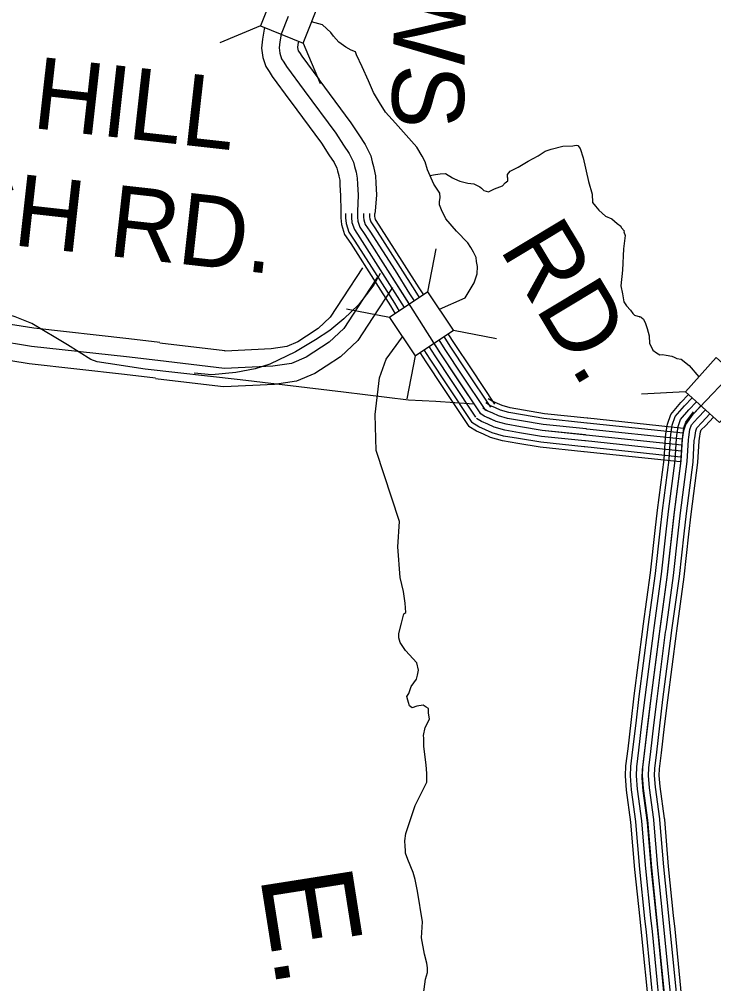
# Model space of a CAD drawing. Extents: x 1551132 to 1791609, y 378168 to 563823.
# Drawn here: x 1647521 to 1651105, y 423447 to 428427 of the extents above; entities that cross this region are included whole.
import ezdxf

# ---------------------------------------------------------------- set-up
doc = ezdxf.new("R2010")
doc.units = 0
for name, color, linetype in [('DESIGN - DRAINAGE - Bridges and Cross Drains Size Text', 7, 'Continuous'), ('DESIGN - ROW - Right-of-Way and Easement Labels', 7, 'Continuous'), ('DESIGN - TRANSPORTATION - Text', 7, 'Continuous'), ('SURVEY - DRAINAGE - Storm Sewer', 7, 'Continuous'), ('SURVEY - PROPERTY - Owners', 7, 'Continuous'), ('SURVEY - TRANSPORTATION - Roads', 7, 'Continuous')]:
    doc.layers.add(name, color=color, linetype=linetype)

msp = doc.modelspace()

# ---------------------------------------------------------------- linework, layer by layer
at = {"layer": 'DESIGN - TRANSPORTATION - Text'}
for points in [[(1649689.434, 426930.053), (1649822.414, 426988.779), (1649868.13, 427066.006), (1649884.904, 427111.841), (1649886.863, 427150.908), (1649881.504, 427176.017), (1649879.763, 427196.076), (1649866.13, 427224.294), (1649852.447, 427248.503), (1649836.764, 427272.737), (1649777.582, 427333.572), (1649722.417, 427396.356), (1649701.017, 427442.699), (1649689.359, 427468.883), (1649689.559, 427484.909), (1649693.834, 427506.893), (1649692.117, 427528.952), (1649660.726, 427575.419), (1649627.694, 427649.946), (1649616.211, 427690.156), (1649600.611, 427720.398), (1649573.212, 427766.816), (1649462.865, 427890.386), (1649411.624, 427947.121), (1649380.292, 427997.589), (1649348.951, 428048.065), (1649323.735, 428108.475), (1649290.677, 428181.002), (1649261.495, 428243.47), (1649255.703, 428259.571), (1649233.82, 428267.854), (1649206.029, 428282.221), (1649170.388, 428308.705), (1649142.797, 428339.098), (1649129.064, 428359.298), (1649086.182, 428398.174), (1649029.933, 428413.641)], [(1649639.444, 427619.512), (1649669.476, 427625.312), (1649693.476, 427629.146), (1649721.467, 427630.954), (1649757.266, 427608.679), (1649767.207, 427602.595), (1649795.098, 427590.387), (1649836.981, 427580.086), (1649866.93, 427577.87), (1649898.779, 427561.628), (1649906.729, 427555.561), (1649918.629, 427543.46), (1649942.545, 427535.285), (1649974.627, 427551.086), (1650014.701, 427566.828), (1650028.801, 427582.753), (1650042.868, 427592.67), (1650042.984, 427608.696), (1650041.001, 427610.712), (1650041.101, 427624.729), (1650055.217, 427642.655), (1650095.325, 427662.405), (1650147.498, 427694.09), (1650199.647, 427721.765), (1650235.788, 427745.549), (1650265.829, 427755.358), (1650325.886, 427770.967), (1650377.843, 427772.608), (1650395.851, 427776.483), (1650403.834, 427774.425), (1650415.717, 427760.325), (1650431.35, 427712.148), (1650458.424, 427589.787), (1650477.924, 427523.552), (1650479.616, 427481.484), (1650495.448, 427461.342), (1650513.29, 427441.191), (1650547.031, 427410.907), (1650578.897, 427396.674), (1650606.696, 427372.44), (1650626.57, 427358.281), (1650628.52, 427352.264), (1650644.362, 427332.122), (1650642.345, 427330.13), (1650648.195, 427310.063), (1650639.703, 427242.028), (1650634.903, 427131.9), (1650626.312, 427049.84), (1650634.012, 427009.73), (1650641.695, 426967.621), (1650655.536, 426947.495), (1650675.352, 426925.32), (1650687.21, 426907.211), (1650697.143, 426899.136), (1650725.059, 426890.927), (1650723.06, 426890.944), (1650731.034, 426888.885), (1650735.001, 426884.852), (1650742.951, 426878.785), (1650752.775, 426856.685), (1650762.575, 426830.584), (1650772.292, 426792.458), (1650773.992, 426752.39), (1650785.825, 426730.273), (1650791.724, 426718.214), (1650809.607, 426704.072), (1650827.515, 426693.939), (1650841.515, 426695.839), (1650859.465, 426691.714), (1650889.406, 426687.497), (1650901.347, 426681.405), (1650915.288, 426675.297), (1650937.238, 426671.138), (1650978.962, 426638.804), (1651029.002, 426581.352)], [(1649358.675, 426386.963), (1649380.241, 426574.793), (1649414.248, 426672.329), (1649499.355, 426786.932)], [(1649607.35, 423393.451), (1649617.867, 423471.503), (1649628.083, 423505.488), (1649628.242, 423529.53), (1649624.4, 423553.589), (1649612.7, 423599.748), (1649597.259, 423684.001), (1649601.792, 423766.094), (1649576.835, 423924.532), (1649565.227, 423984.717), (1649553.46, 424020.851), (1649525.911, 424089.161), (1649514.12, 424121.295), (1649514.211, 424135.321), (1649512.361, 424157.371), (1649510.545, 424185.43), (1649516.795, 424223.448), (1649563.735, 424367.344), (1649602.226, 424443.196), (1649624.517, 424487.113), (1649624.817, 424533.181), (1649621.109, 424577.282), (1649609.726, 424671.518), (1649610.009, 424715.586), (1649608.101, 424729.62), (1649616.368, 424769.629), (1649630.534, 424795.572), (1649638.667, 424815.547), (1649632.851, 424843.631), (1649633.009, 424867.673), (1649621.059, 424875.765), (1649605.126, 424885.899), (1649573.094, 424880.115), (1649549.036, 424872.273), (1649535.103, 424882.39), (1649529.211, 424898.457), (1649527.295, 424910.491), (1649521.42, 424930.558), (1649531.528, 424946.517), (1649543.761, 424982.485), (1649572.01, 425020.352), (1649576.144, 425040.353), (1649582.31, 425066.354), (1649572.561, 425104.48), (1649514.97, 425166.99), (1649487.246, 425209.257), (1649479.404, 425233.35), (1649479.554, 425255.383), (1649493.904, 425309.377), (1649506.221, 425357.361), (1649516.254, 425363.303), (1649512.57, 425411.404), (1649504.962, 425471.556), (1649487.438, 425543.799), (1649474.48, 425702.154), (1649483.346, 425834.299), (1649363.474, 426199.6), (1649358.675, 426386.963)]]:
    msp.add_lwpolyline(points, dxfattribs=at)
at = {"layer": 'SURVEY - DRAINAGE - Storm Sewer'}
for p, q in [((1648765.471, 428393.363), (1648556.414, 428304.608)), ((1648985.723, 428304.36), (1649074.487, 428095.312)), ((1649629.107, 427019.468), (1649672.443, 427242.428)), ((1649432.135, 426886.596), (1649209.183, 426929.933)), ((1649762.004, 426822.48), (1649984.93, 426779.168)), ((1649564.965, 426689.641), (1649521.645, 426466.715)), ((1650958.95, 426503.296), (1650732.141, 426491.416))]:
    msp.add_line(p, q, dxfattribs=at)
for points in [[(1648765.471, 428393.363), (1648985.773, 428304.343), (1649074.793, 428524.654), (1648854.474, 428613.658)], [(1649432.135, 426886.596), (1649564.99, 426689.616), (1649762.004, 426822.48), (1649629.107, 427019.468)], [(1650958.95, 426503.296), (1651135.546, 426344.317), (1651294.5, 426520.88), (1651117.937, 426679.867)]]:
    msp.add_lwpolyline(points, close=True, dxfattribs=at)
at = {"layer": 'SURVEY - PROPERTY - Owners'}
for points in [[(1648909.47, 428441.208), (1648872.587, 428349.439), (1648865.404, 428311.088), (1648861.904, 428279.454), (1648866.112, 428251.27), (1648875.354, 428223.253), (1648887.17, 428205.111), (1648900.945, 428182.952), (1648991.701, 428059.923), (1649155.455, 427838.068), (1649194.846, 427777.616), (1649224.395, 427733.273), (1649245.953, 427689.006), (1649251.736, 427666.922), (1649259.436, 427636.813), (1649265.136, 427606.72), (1649266.827, 427574.661), (1649270.269, 427518.551), (1649267.452, 427434.466), (1649267.161, 427404.431), (1649268.961, 427384.389), (1649278.66, 427354.255), (1649304.276, 427315.962), (1649434.223, 427112.457), (1649692.125, 426705.455), (1649901.22, 426390.347)], [(1648788.706, 428383.974), (1648785.081, 428374.948), (1648775.623, 428324.447), (1648770.448, 428277.712), (1648777.548, 428230.211), (1648792.905, 428183.635), (1648810.638, 428156.401), (1648825.813, 428132), (1648917.677, 428007.464), (1648918.719, 428006.055), (1649080.907, 427786.325), (1649119.106, 427727.698), (1649145.522, 427688.055), (1649160.48, 427657.346), (1649163.921, 427644.188), (1649170.055, 427620.229), (1649170.846, 427617.129), (1649174.88, 427595.836), (1649176.271, 427569.494), (1649179.471, 427517.293), (1649180.371, 427438.441), (1649180.371, 427426.324)], [(1648962.002, 428314.663), (1648958.735, 428297.205), (1648956.968, 428281.263), (1648958.177, 428273.162), (1648961.052, 428264.437), (1648966.718, 428255.737), (1648979.043, 428235.92), (1649066.541, 428117.308), (1649067.566, 428115.925), (1649232.953, 427891.853), (1649273.577, 427829.501), (1649306.385, 427780.275), (1649334.801, 427721.915), (1649343.017, 427690.556), (1649349.292, 427666.038), (1649351.525, 427657.271), (1649358.959, 427618.029), (1649360.967, 427580.036), (1649364.658, 427519.86), (1649358.492, 427436.332), (1649355.85, 427423.682)], [(1650999.136, 426388.181), (1651234.739, 426636.637), (1651378.127, 426785.458), (1651566.123, 426997.939), (1651612.572, 427045.565), (1651679.096, 427103), (1651817.784, 427179.777), (1651998.722, 427284.188), (1652121.385, 427357.107), (1652177.526, 427374.599), (1652225.616, 427386.149), (1652261.657, 427391.816), (1652327.564, 427385.174), (1652539.234, 427361.124), (1653150.228, 427287.189), (1653709.273, 427215.754), (1654418.581, 427121.668)], [(1648246.609, 426757.839), (1648085.946, 426776.881), (1647596.491, 426831.449), (1647408.537, 426861.041), (1647360.622, 426868.125), (1647346.797, 426873.466), (1647232.508, 426944.427), (1647042.504, 427058.621), (1646944.848, 427097.505), (1646907.682, 427109.506), (1646858.475, 427116.273), (1646810.885, 427111.181), (1646765.427, 427100.922), (1646727.445, 427080.255), (1646690.454, 427049.096), (1646676.529, 427019.92), (1646610.073, 426849.599)], [(1649292.86, 427143.866), (1649191.67, 426988.895), (1649126.055, 426888.509), (1649063.965, 426830.708), (1649003.316, 426791.174), (1648958.959, 426762.256), (1648901.377, 426737.455), (1648820.454, 426726.013), (1648583.46, 426713.963), (1648581.576, 426714.188), (1648246.284, 426754.272)], [(1649383.549, 427114.824), (1649351.925, 427055.781), (1649271.819, 426952.453), (1649195.929, 426880.759), (1649124.247, 426819.608), (1649050.465, 426771.106), (1648947.168, 426709.955), (1648814.354, 426646.695), (1648738.464, 426621.394), (1648639.383, 426602.41), (1648515.003, 426591.868), (1648424.355, 426600.302)], [(1649368.808, 427094.273), (1649267.61, 426939.286), (1649195.937, 426829.633), (1649120.047, 426758.989), (1649001.983, 426682.021), (1648926.101, 426649.336), (1648829.12, 426635.628), (1648580.36, 426622.977), (1648235.518, 426664.203)], [(1648235.518, 426664.203), (1648075.171, 426683.204), (1647583.933, 426737.971), (1647394.312, 426767.822), (1647336.422, 426776.381), (1647304.556, 426788.706), (1647183.351, 426863.958), (1647000.505, 426973.852), (1646912.891, 427008.736), (1646886.616, 427017.22), (1646857.042, 427021.287), (1646826.326, 427018.003), (1646798.977, 427011.828), (1646780.885, 427001.986), (1646766.777, 426990.103), (1646763.111, 426982.419), (1646759.519, 426973.219)], [(1649447.756, 427042.722), (1649346.55, 426887.71), (1649268.577, 426768.431), (1649178.346, 426684.437), (1649104.339, 426636.186), (1649046.707, 426598.619), (1648951.801, 426557.734), (1648838.128, 426541.667), (1648577.135, 426528.4), (1648559.618, 426530.491), (1648224.326, 426570.576)], [(1648224.843, 426574.126), (1648064.813, 426593.084), (1647571.85, 426648.044), (1647380.629, 426678.145), (1647313.139, 426688.128), (1647263.924, 426707.162), (1647136.069, 426786.547), (1646960.098, 426892.3), (1646882.15, 426923.343), (1646866.35, 426928.443), (1646855.667, 426929.909), (1646841.184, 426928.368), (1646803.226, 426801.156)], [(1649868.013, 426440.398), (1649671.667, 426453.323), (1649529.804, 426460.69), (1649194.362, 426501.949), (1648661.224, 426565.117), (1648169.986, 426619.885), (1647980.365, 426649.736), (1647922.475, 426658.294), (1647890.609, 426670.62), (1647769.404, 426745.872), (1647586.558, 426855.766), (1647498.943, 426890.65), (1647472.669, 426899.134), (1647443.095, 426903.201), (1647412.379, 426899.917), (1647385.029, 426893.742), (1647366.938, 426883.9), (1647360.105, 426878.142)], [(1650941.046, 426228.268), (1650446.491, 426280.278), (1650220.713, 426304.028), (1650108.865, 426322.912), (1650034.975, 426335.487), (1649983.018, 426350.346), (1649921.303, 426378.413), (1649897.412, 426392.614)], [(1650857.346, 423315.4), (1650818.147, 423708.194), (1650784.457, 424032.86), (1650764.215, 424279.325), (1650741.383, 424443.705), (1650735.841, 424509.598), (1650738.158, 424551.866), (1650748.766, 424637.893), (1650780.69, 424909.992), (1650825.123, 425254.084), (1650865.189, 425546.15), (1650901.48, 425870.275), (1650935.346, 426134.349), (1650942.146, 426246.444), (1650950.554, 426304.453), (1650960.762, 426334.413), (1650999.136, 426388.181)]]:
    msp.add_lwpolyline(points, dxfattribs=at)
at = {"layer": 'SURVEY - TRANSPORTATION - Roads'}
for points in [[(1649180.638, 427425.04), (1649180.404, 427400.965), (1649183.454, 427367.014), (1649199.837, 427316.129), (1649231.686, 427268.511), (1649361.058, 427065.914), (1649436.406, 426947.003)], [(1649205.354, 427424.799), (1649205.137, 427401.956), (1649207.829, 427371.964), (1649222.303, 427326.996), (1649252.378, 427282.037), (1649381.916, 427079.181), (1649457.289, 426960.228)], [(1649236.353, 427424.499), (1649236.145, 427403.19), (1649238.395, 427378.181), (1649250.486, 427340.621), (1649278.327, 427298.995), (1649408.065, 427095.815), (1649483.472, 426976.829)], [(1649267.352, 427424.199), (1649267.161, 427404.431), (1649268.961, 427384.389), (1649278.66, 427354.255), (1649304.276, 427315.962), (1649434.223, 427112.457), (1649692.125, 426705.455), (1649901.22, 426390.347)], [(1649267.352, 427424.199), (1649267.161, 427404.431), (1649268.961, 427384.389), (1649278.66, 427354.255), (1649304.276, 427315.962), (1649434.223, 427112.457), (1649509.655, 426993.421)], [(1649298.352, 427423.899), (1649298.177, 427405.673), (1649299.526, 427390.598), (1649306.835, 427367.889), (1649330.226, 427332.93), (1649460.381, 427129.099), (1649535.837, 427010.013)], [(1649329.351, 427423.599), (1649329.184, 427406.907), (1649330.092, 427396.815), (1649335.017, 427381.514), (1649356.175, 427349.888), (1649486.53, 427145.733), (1649562.02, 427026.613)], [(1649355.067, 427423.349), (1649354.917, 427407.94), (1649355.45, 427401.965), (1649358.392, 427392.823), (1649377.7, 427363.964), (1649508.23, 427159.542), (1649583.745, 427040.372)], [(1650999.136, 426388.181), (1651234.739, 426636.637), (1651378.127, 426785.458), (1651566.123, 426997.939), (1651612.572, 427045.565), (1651679.096, 427103), (1651817.784, 427179.777), (1651998.722, 427284.188), (1652121.385, 427357.107), (1652177.526, 427374.599), (1652225.616, 427386.149), (1652261.657, 427391.816), (1652327.564, 427385.174), (1652539.234, 427361.124), (1653150.228, 427287.189), (1653709.273, 427215.754), (1654418.581, 427121.668)], [(1649535.829, 427010.021), (1649559.545, 426972.595)], [(1649562.012, 427026.613), (1649585.253, 426989.937)], [(1649583.736, 427040.38), (1649606.602, 427004.304)], [(1649436.398, 426947.011), (1649461.922, 426906.727)], [(1649457.281, 426960.245), (1649482.439, 426920.544)], [(1649483.464, 426976.837), (1649508.138, 426937.894)], [(1649509.646, 426993.429), (1649533.837, 426955.253)], [(1649733.849, 426803.483), (1649765.724, 426753.19), (1649853.171, 426621.403)], [(1649661.076, 426754.448), (1649692.125, 426705.455), (1649780.081, 426572.902)], [(1649686.784, 426771.79), (1649718.133, 426722.322), (1649805.914, 426590.044)], [(1649712.541, 426789.074), (1649744.149, 426739.198), (1649831.739, 426607.186)], [(1649589.153, 426705.955), (1649619.369, 426658.27), (1649707.825, 426524.95)], [(1649609.636, 426719.789), (1649640.101, 426671.712), (1649728.424, 426538.617)], [(1649635.352, 426737.139), (1649666.118, 426688.588), (1649754.249, 426555.759)], [(1649831.73, 426607.202), (1649952.877, 426424.631)], [(1649853.163, 426621.42), (1649974.31, 426438.848)], [(1649754.24, 426555.776), (1649875.387, 426373.205)], [(1649780.073, 426572.918), (1649901.22, 426390.347)], [(1649805.906, 426590.06), (1649927.053, 426407.489)], [(1649707.816, 426524.967), (1649841.163, 426324.003)], [(1649728.416, 426538.634), (1649857.38, 426344.279)], [(1649988.685, 426443.04), (1649961.519, 426455.39), (1649941.719, 426467.157)], [(1650936.213, 426447.849), (1650975.028, 426488.783)], [(1650954.146, 426430.848), (1650993.386, 426472.225)], [(1650976.645, 426409.515), (1651016.502, 426451.549)], [(1649965.627, 426392.314), (1649935.678, 426405.931), (1649913.253, 426419.264)], [(1649978.452, 426420.539), (1649950.061, 426433.448), (1649929.086, 426445.915)], [(1650450.307, 426342.221), (1650229.121, 426365.488), (1650119.223, 426384.038), (1650048.742, 426396.039), (1650004.493, 426408.689), (1649978.435, 426420.539)], [(1650452.891, 426366.805), (1650232.479, 426389.989), (1650123.357, 426408.414), (1650054.225, 426420.173), (1650013.051, 426431.956), (1649988.668, 426443.04)], [(1650858.763, 423327.467), (1650819.564, 423720.261), (1650785.873, 424044.927), (1650765.632, 424291.392), (1650742.799, 424455.772), (1650737.258, 424521.665), (1650739.575, 424563.933), (1650750.183, 424649.96), (1650782.107, 424922.059), (1650826.54, 425266.151), (1650866.605, 425558.217), (1650902.896, 425882.342), (1650936.762, 426146.416), (1650943.562, 426258.511), (1650951.971, 426316.52), (1650962.179, 426346.48), (1651000.553, 426400.248)], [(1650859.006, 426286.595), (1650866.323, 426337.129), (1650883.305, 426386.956), (1650936.013, 426447.866)], [(1650884.455, 426282.911), (1650891.439, 426331.087), (1650906.43, 426375.089), (1650954.462, 426430.732)], [(1650915.13, 426278.461), (1650921.705, 426323.804), (1650934.304, 426360.788), (1650976.853, 426409.906)], [(1650999.136, 426388.181), (1651039.535, 426430.782)], [(1651021.627, 426366.847), (1651062.593, 426410.048)], [(1649939.961, 426335.879), (1649906.928, 426350.896), (1649881.571, 426365.963)], [(1650941.046, 426228.268), (1650446.491, 426280.278), (1650220.713, 426304.028), (1650108.865, 426322.912), (1650034.975, 426335.487), (1649983.018, 426350.346), (1649921.303, 426378.413), (1649897.412, 426392.614)], [(1649952.794, 426364.096), (1649921.303, 426378.413), (1649897.412, 426392.614)], [(1650443.824, 426280.561), (1650220.713, 426304.028), (1650108.865, 426322.912), (1650034.975, 426335.487), (1649983.018, 426350.346), (1649952.777, 426364.096)], [(1650447.066, 426311.395), (1650224.921, 426334.754), (1650114.048, 426353.479), (1650041.859, 426365.763), (1649993.751, 426379.522), (1649965.61, 426392.314)], [(1650950.112, 426314.512), (1650455.574, 426366.522), (1650452.916, 426366.797)], [(1650945.812, 426274.019), (1650951.971, 426316.52), (1650962.179, 426346.48), (1650999.253, 426388.556)], [(1650976.495, 426269.578), (1650982.236, 426309.237), (1650990.053, 426332.171), (1651021.519, 426366.88)], [(1651044.127, 426345.513), (1651085.592, 426389.239)], [(1651062.785, 426327.821), (1651104.717, 426372.047)], [(1649916.495, 426284.244), (1649880.621, 426300.553), (1649841.163, 426324.003)], [(1649927.136, 426307.653), (1649892.545, 426323.378), (1649857.38, 426344.279)], [(1650437.341, 426218.901), (1650212.304, 426242.568), (1650098.507, 426261.785), (1650021.209, 426274.936), (1649961.544, 426292.003), (1649927.12, 426307.653)], [(1650440.582, 426249.727), (1650216.504, 426273.302), (1650103.682, 426292.344), (1650028.092, 426305.211), (1649972.285, 426321.17), (1649939.944, 426335.879)], [(1650944.287, 426259.102), (1650449.741, 426311.112), (1650447.066, 426311.387)], [(1650947.529, 426289.928), (1650452.991, 426341.938), (1650450.316, 426342.221)], [(1651007.169, 426265.127), (1651012.502, 426301.953), (1651017.927, 426317.871), (1651043.66, 426345.263)], [(1651031.627, 426261.586), (1651036.635, 426296.145), (1651040.152, 426306.462), (1651062.626, 426327.871)], [(1650434.649, 426193.325), (1650208.813, 426217.076), (1650094.207, 426236.426), (1650015.501, 426249.818), (1649952.644, 426267.802), (1649916.47, 426284.244)], [(1650941.046, 426228.268), (1650446.491, 426280.278), (1650443.807, 426280.561)], [(1650803.949, 425786.981), (1650815.807, 425892.801), (1650849.389, 426154.658), (1650856.231, 426267.469), (1650859.006, 426286.62)], [(1650829.506, 425784.115), (1650841.34, 425889.734), (1650875.006, 426152.241), (1650881.83, 426264.844), (1650884.455, 426282.928)], [(1650860.314, 425780.665), (1650872.114, 425886.042), (1650905.88, 426149.333), (1650912.696, 426261.677), (1650915.13, 426278.486)], [(1650891.122, 425777.215), (1650902.896, 425882.342), (1650936.762, 426146.416), (1650943.562, 426258.511), (1650945.812, 426274.036)], [(1650921.929, 425773.765), (1650933.679, 425878.642), (1650967.645, 426143.499), (1650974.428, 426255.344), (1650976.495, 426269.586)], [(1650952.737, 425770.314), (1650964.453, 425874.951), (1650998.519, 426140.591), (1651005.294, 426252.177), (1651007.169, 426265.144)], [(1650977.295, 425767.564), (1650988.994, 425872), (1651023.144, 426138.266), (1651029.902, 426249.652), (1651031.627, 426261.594)], [(1650934.563, 426166.608), (1650439.991, 426218.618), (1650437.299, 426218.901)], [(1650937.804, 426197.434), (1650443.241, 426249.443), (1650440.549, 426249.735)], [(1650931.871, 426141.033), (1650437.299, 426193.042), (1650434.599, 426193.325)], [(1650741.7, 425293.102), (1650779.557, 425569.059), (1650803.957, 425786.99)], [(1650767.174, 425289.602), (1650805.074, 425565.884), (1650829.515, 425784.131)], [(1650797.89, 425285.393), (1650835.839, 425562.051), (1650860.322, 425780.681)], [(1650828.598, 425281.177), (1650866.605, 425558.217), (1650891.13, 425777.231)], [(1650859.305, 425276.96), (1650897.371, 425554.384), (1650921.938, 425773.781)], [(1650890.021, 425272.751), (1650928.137, 425550.55), (1650952.745, 425770.331)], [(1650914.504, 425269.393), (1650952.662, 425547.5), (1650977.303, 425767.581)], [(1650678.926, 424795.347), (1650695.051, 424932.784), (1650739.592, 425277.735), (1650741.708, 425293.135)], [(1650704.467, 424792.347), (1650720.575, 424929.642), (1650765.083, 425274.343), (1650767.183, 425289.635)], [(1650735.25, 424788.739), (1650751.341, 424925.851), (1650795.815, 425270.243), (1650797.899, 425285.41)], [(1650766.041, 424785.122), (1650782.107, 424922.059), (1650826.54, 425266.151), (1650828.606, 425281.193)], [(1650796.832, 424781.505), (1650812.873, 424918.267), (1650857.264, 425262.059), (1650859.314, 425276.976)], [(1650827.614, 424777.897), (1650843.639, 424914.475), (1650887.996, 425257.959), (1650890.03, 425272.751)], [(1650852.164, 424775.013), (1650868.172, 424911.45), (1650912.496, 425254.693), (1650914.512, 425269.393)], [(1650678.451, 424281.317), (1650678.417, 424281.717), (1650655.593, 424446.055), (1650649.343, 424520.382), (1650652.152, 424571.708), (1650663.093, 424660.435), (1650678.926, 424795.355)], [(1650704.084, 424283.45), (1650703.992, 424284.559), (1650681.159, 424448.905), (1650675.118, 424520.757), (1650677.784, 424569.433), (1650688.626, 424657.368), (1650704.467, 424792.364)], [(1650734.974, 424286.017), (1650734.808, 424287.975), (1650711.983, 424452.338), (1650706.184, 424521.215), (1650708.675, 424566.683), (1650719.408, 424653.66), (1650735.25, 424788.747)], [(1650765.865, 424288.584), (1650765.632, 424291.392), (1650742.799, 424455.772), (1650737.258, 424521.665), (1650739.575, 424563.933), (1650750.183, 424649.96), (1650766.041, 424785.139)], [(1650796.756, 424291.151), (1650796.456, 424294.809), (1650773.615, 424459.205), (1650768.332, 424522.115), (1650770.474, 424561.183), (1650780.957, 424646.26), (1650796.832, 424781.53)], [(1650827.647, 424293.717), (1650827.272, 424298.226), (1650804.44, 424462.638), (1650799.398, 424522.573), (1650801.365, 424558.433), (1650811.74, 424642.551), (1650827.614, 424777.913)], [(1650852.28, 424295.767), (1650851.855, 424300.959), (1650829.014, 424465.38), (1650824.173, 424522.932), (1650825.998, 424556.241), (1650836.281, 424639.601), (1650852.164, 424775.038)], [(1650724.999, 423781.72), (1650698.534, 424036.811), (1650678.434, 424281.417)], [(1650750.582, 423784.379), (1650724.141, 424039.186), (1650704.067, 424283.525)], [(1650781.415, 423787.579), (1650755.007, 424042.061), (1650734.958, 424286.059)], [(1650812.247, 423790.779), (1650785.873, 424044.927), (1650765.857, 424288.6)], [(1650843.08, 423793.979), (1650816.739, 424047.794), (1650796.756, 424291.142)], [(1650873.913, 423797.179), (1650847.605, 424050.669), (1650827.647, 424293.676)], [(1650898.495, 423799.729), (1650872.221, 424052.953), (1650852.28, 424295.701)], [(1650774.373, 423285.599), (1650771.431, 423319.292), (1650732.299, 423711.377), (1650724.999, 423781.745)], [(1650799.989, 423287.841), (1650797.031, 423321.692), (1650757.882, 423713.985), (1650750.582, 423784.396)], [(1650830.872, 423290.541), (1650827.897, 423324.575), (1650788.723, 423717.119), (1650781.415, 423787.596)], [(1650861.754, 423293.241), (1650858.763, 423327.467), (1650819.564, 423720.261), (1650812.247, 423790.796)], [(1650892.637, 423295.941), (1650889.629, 423330.359), (1650850.405, 423723.402), (1650843.08, 423793.996)], [(1650923.52, 423298.641), (1650920.495, 423333.242), (1650881.246, 423726.536), (1650873.913, 423797.196)], [(1650948.136, 423300.791), (1650945.102, 423335.551), (1650905.837, 423729.044), (1650898.495, 423799.746)]]:
    msp.add_lwpolyline(points, dxfattribs=at)

# ---------------------------------------------------------------- texts
at = {"layer": 'DESIGN - DRAINAGE - Bridges and Cross Drains Size Text'}
msp.add_text('E.', height=475.0118, rotation=278.951886, dxfattribs=at).set_placement((1648762.364, 424005.171))
at = {"layer": 'DESIGN - ROW - Right-of-Way and Easement Labels'}
for s, height, rotation, p in [('MATHEWS', 370.0097, 268.790072, (1649496.249, 430395.402)), ('HILL', 369.9915, 353.638478, (1647581.365, 427866.153)), ('CHURCH RD.', 369.9915, 353.638478, (1645706.376, 427458.883)), ('RD.', 370.0046, 301.074628, (1649996.027, 427242.844))]:
    msp.add_text(s, height=height, rotation=rotation, dxfattribs=at).set_placement(p)

doc.saveas('drawing.dxf')
